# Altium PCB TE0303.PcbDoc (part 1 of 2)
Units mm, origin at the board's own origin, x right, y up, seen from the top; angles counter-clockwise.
Board outline 115 x 70 mm, 4 copper layers (L 01 (Top), L 02, L 03, L 04 (Bot)), stack 1.564 mm thick; 42 components, 141 nets, 429 pads, 134 vias.
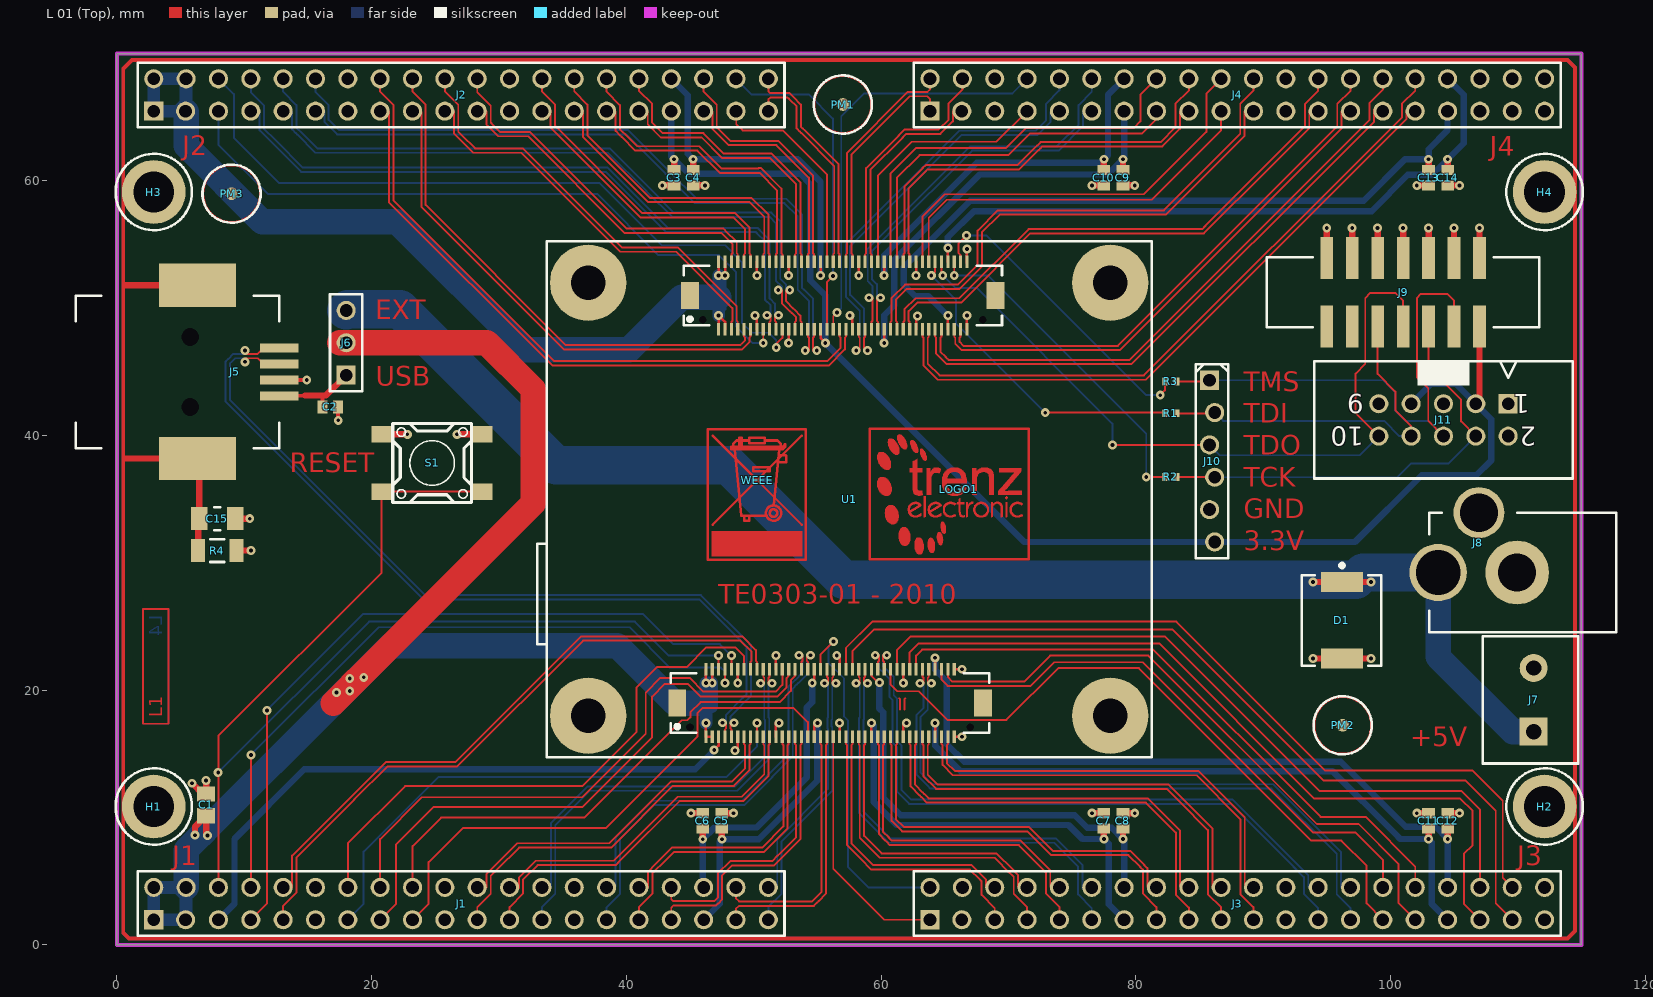
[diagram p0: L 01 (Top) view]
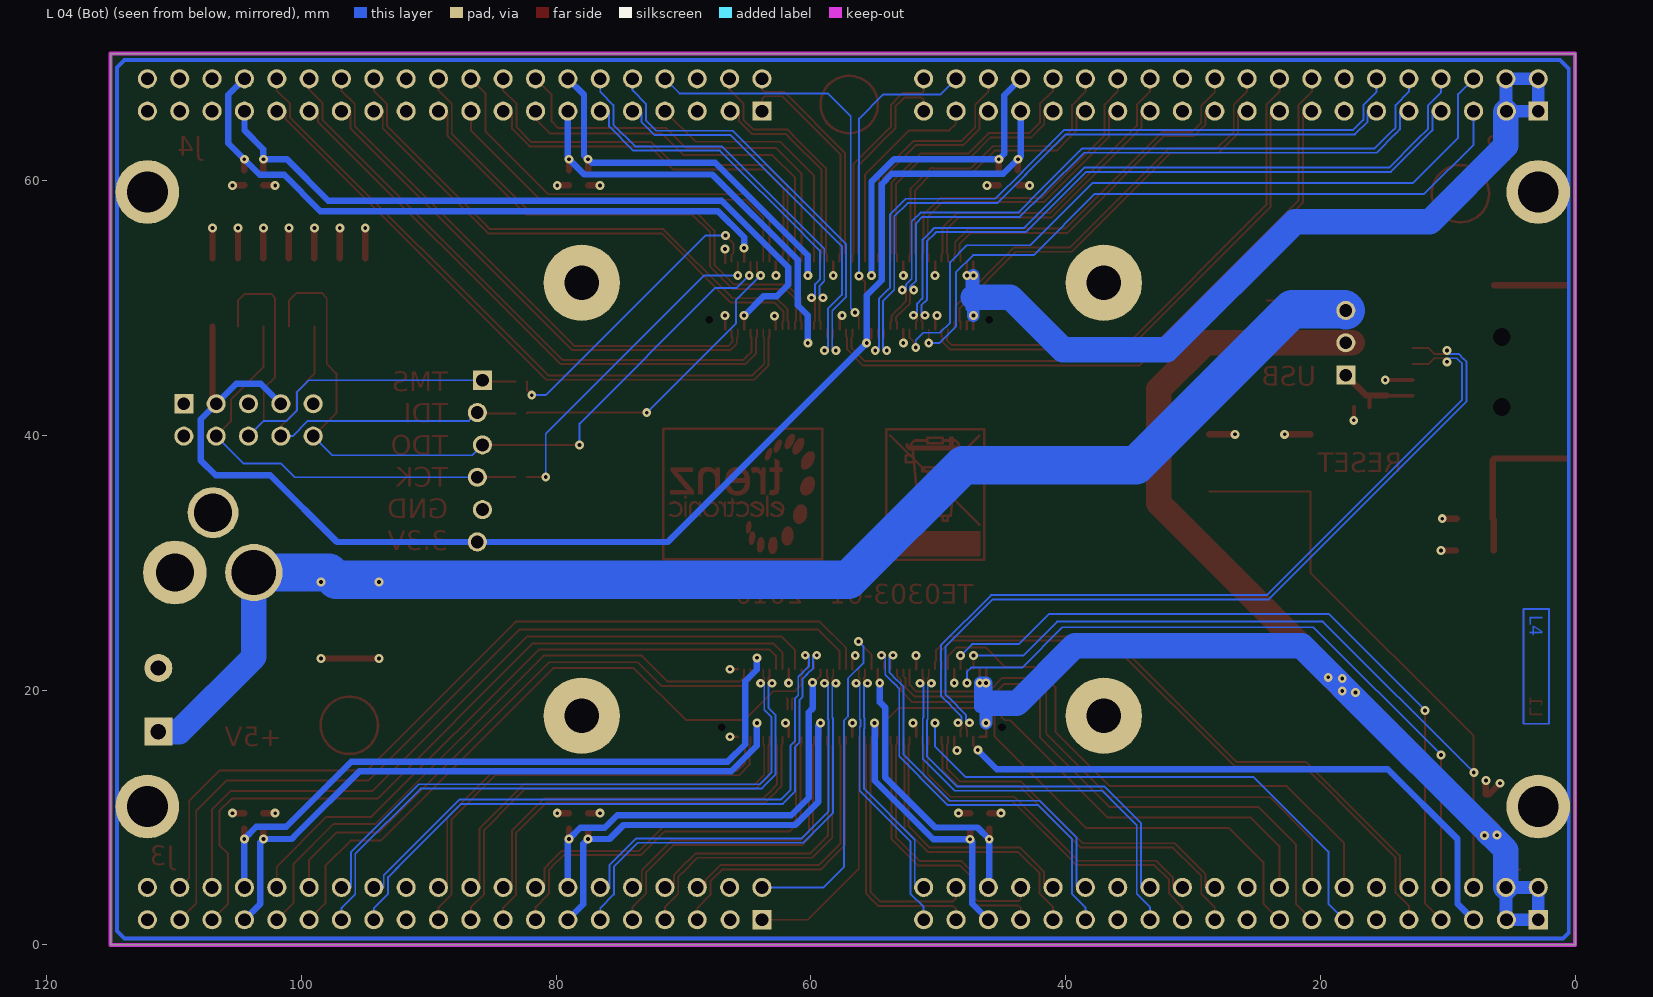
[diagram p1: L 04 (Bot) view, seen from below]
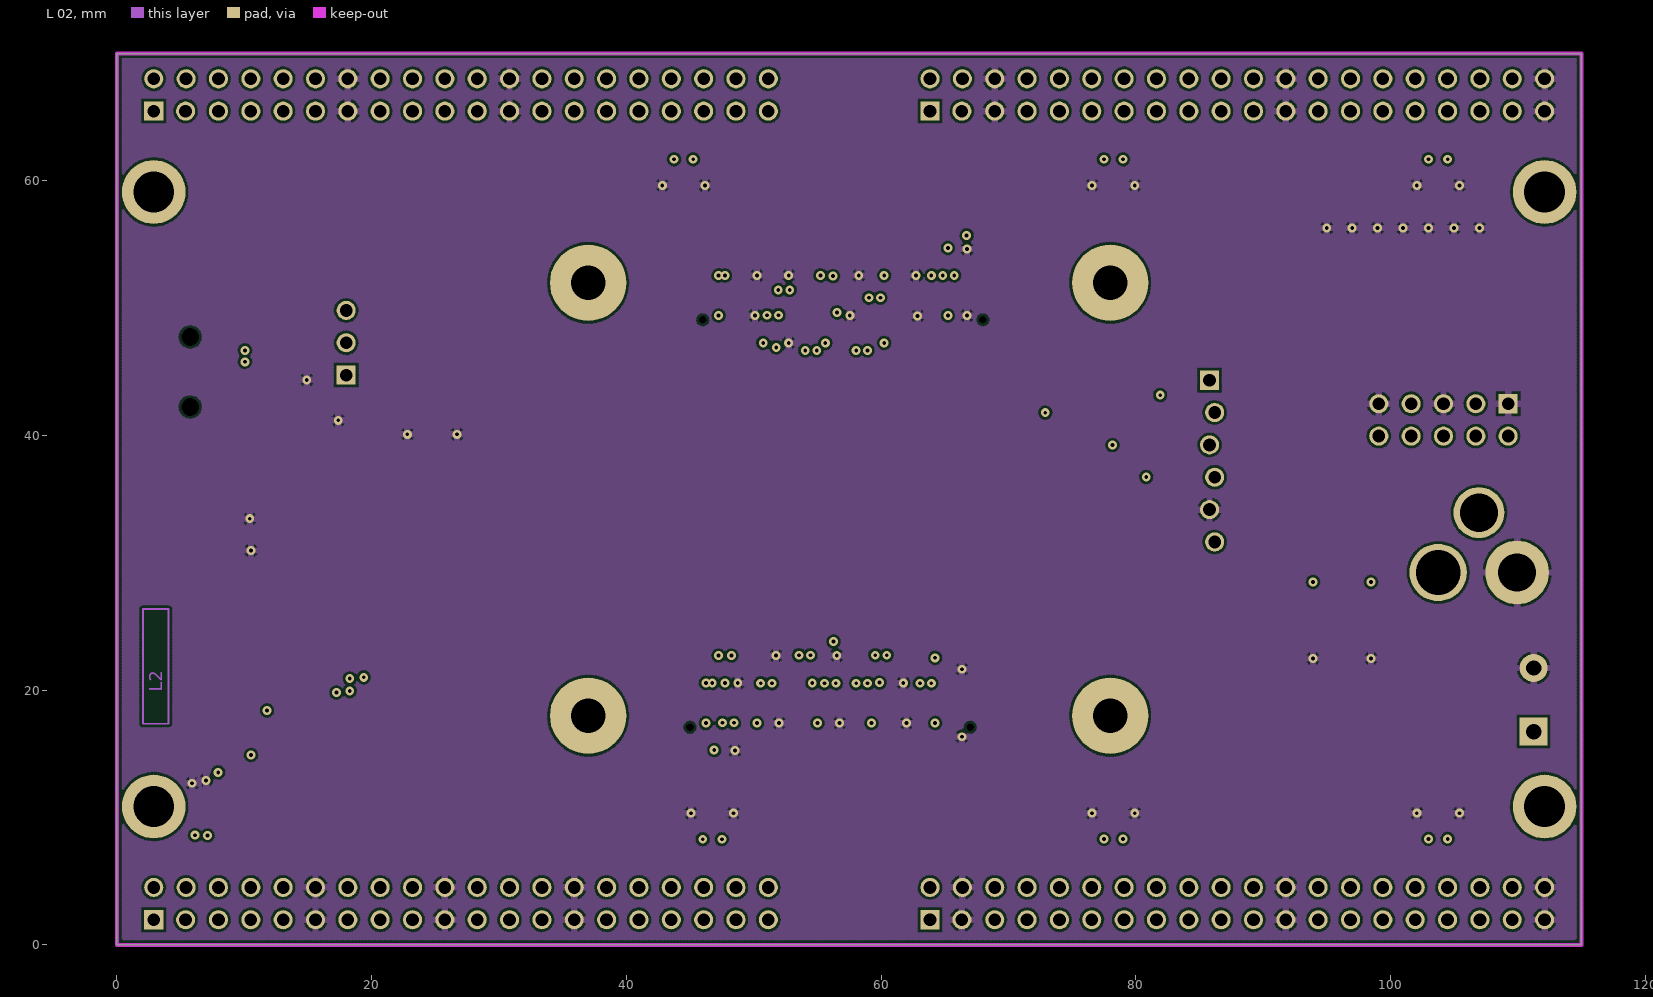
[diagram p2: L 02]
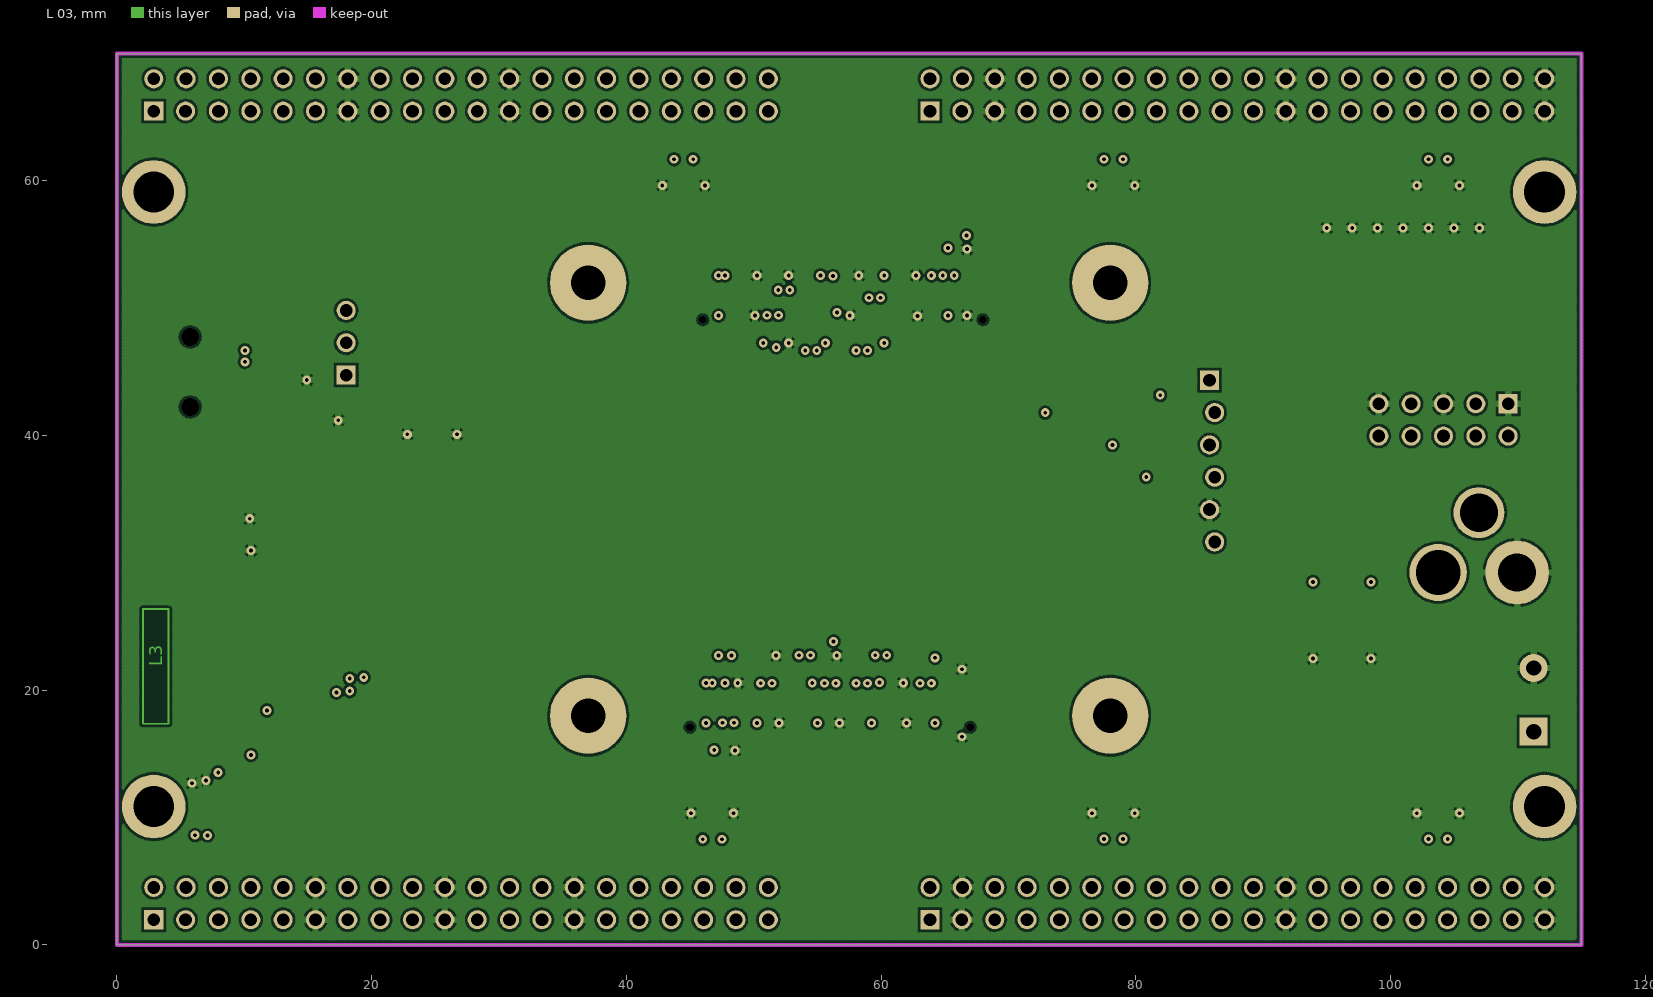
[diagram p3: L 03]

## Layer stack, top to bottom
L 01 (Top): signal copper 0.05
Dielectric: core 0.134, FR-4, Dk 4.8
L 02: signal copper 0.033
Dielectric: prepreg 1.13, FR-4, Dk 4.8
L 03: signal copper 0.033
Dielectric: core 0.134, FR-4, Dk 4.8
L 04 (Bot): signal copper 0.05

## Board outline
0,0 0,70 115,70 115,0

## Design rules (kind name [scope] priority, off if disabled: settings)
Clearance Clearance_Polygon [(InPolygon)] p1: gap=0.2
Clearance [All] p2: gap=0.19
ComponentClearance ComponentClearance_WEEE [(InComponent('WEEE'))] p1: gap=-20 collisioncheckmode=3 verticalgap=0.254 showdistances=FALSE
ComponentClearance ComponentClearance_LOGO [(InComponent('LOGO1'))] p2: gap=-50 collisioncheckmode=3 verticalgap=0 showdistances=FALSE
ComponentClearance [All] p3: gap=-0.05 collisioncheckmode=3 verticalgap=0.254 showdistances=FALSE
DiffPairsRouting [All] p1: maxlimit=1 minlimit=0.189 mostfreqgap=1 toplayer_maxgap=0.191 toplayer_prefgap=0.19 midlayer1_mingap=1 midlayer2_mingap=1 bottomlayer_maxgap=0.191 bottomlayer_prefgap=0.19 maxuncoupledlength=12.7
FabricationTestPointUsage TestPointUsage [All] p1: valid=0 allowmultiple=FALSE
FabricationTestpoint Testpoint [All] p1: side=3 testpointundercomponent=TRUE minsize=1.016 maxsize=2.54 preferedsize=1.524 minholesize=0 maxholesize=1.016 preferedholesize=0.813 testpointgrid=0.025 allowsidetop=TRUE allowsidebottom=TRUE usegrid=TRUE gridtolerance=0
HoleSize [All] p1: absolutevalues=TRUE maxlimit=5 minlimit=0.3 maxpercent=80.000 minpercent=20.000
MinimumAnnularRing [Not(InComponent('J7'))] p1: minimumring=0.2
PolygonConnect [All] p1: connectstyle=Relief reliefconductorwidth=0.5 reliefentries=4 polygonreliefangle="90 Angle"
RoutingLayers [All] p1: top layer_v5=TRUE mid layer 1_v5=FALSE mid layer 2_v5=FALSE bottom layer_v5=TRUE
RoutingVias [All] p1: holewidth=0.3 width=0.8 viastyle="Through Hole" minholewidth=0.3 minwidth=0.7 maxholewidth=1 maxwidth=3
SilkscreenOverComponentPads [All] p1: minsilkscreentomaskgap=0.254
SolderMaskExpansion SolderMaskExpansion_VIA [(IsVia)] p1: expansion=-10
SolderMaskExpansion [All] p2: expansion=0.102
Width Width_logo [InComponent(LOGO1)] p1: maxlimit=0.254 minlimit=0.004 preferedwidth=0.254
Width Width_100Ohm [(InNetClass('I100'))] p2: maxlimit=0.15 minlimit=0.15 preferedwidth=0.15
Width [All] p3: maxlimit=3 minlimit=0.15 preferedwidth=0.2
21 further rules are at their usual default settings.

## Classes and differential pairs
component class Main: H1 H2 H3 H4 LOGO1 PM1 PM2 PM3 WEEE
component class Signals: C1 C2 C15 D1 J5 J6 J7 J8 J9 J10 J11 R1 R2 R3 R4 S1 U1
component class Connector: C3 C4 C5 C6 C7 C8 C9 C10 C11 C12 C13 C14 J1 J2 J3 J4
net class I100: B0_L01_N B0_L01_P B0_L03_N B0_L03_P B0_L04_N B0_L04_P B0_L05_N B0_L05_P B0_L06_N B0_L06_P B0_L08_N B0_L08_P B0_L09_N B0_L09_P B0_L15_N B0_L15_P B0_L17_N B0_L17_P B0_L18_N B0_L18_P B0_L19_N B0_L19_P B0_L20_N B0_L20_P B0_L21_N B0_L21_P B0_L23_N B0_L23_P B0_L24_N B0_L24_P B2_GCLK_L13_N B2_GCLK_L13_P B2_L04_N B2_L04_P B2_L05_N B2_L05_P B2_L06_N B2_L06_P B2_L07_N B2_L07_P B2_L09_N B2_L09_P B2_L10_N B2_L10_P B2_L18_N B2_L18_P B2_L19_N B2_L19_P B2_L20_N B2_L20_P B2_L21_N B2_L21_P B2_L22_N B2_L22_P B2_L24_N B2_L24_P B2B_D_N B2B_D_P B3_L01_N B3_L01_P B3_L02_N B3_L02_P B3_L03_N B3_L03_P B3_L07_N B3_L07_P B3_L17_N B3_L17_P B3_L19_N B3_L19_P B3_L20_N B3_L20_P B3_L21_N B3_L21_P B3_L22_N B3_L22_P B3_L23_N B3_L23_P GCLK_L11_N GCLK_L11_P GCLK_L12_N GCLK_L12_P GCLK_L13_N GCLK_L13_P GCLK_L14_N GCLK_L14_P
differential pair B0_L01: +B0_L01_P -B0_L01_N
differential pair B0_L03: +B0_L03_P -B0_L03_N
differential pair B0_L04: +B0_L04_P -B0_L04_N
differential pair B0_L05: +B0_L05_P -B0_L05_N
differential pair B0_L06: +B0_L06_P -B0_L06_N
differential pair B0_L08: +B0_L08_P -B0_L08_N
differential pair B0_L09: +B0_L09_P -B0_L09_N
differential pair B0_L15: +B0_L15_P -B0_L15_N
differential pair B0_L17: +B0_L17_P -B0_L17_N
differential pair B0_L18: +B0_L18_P -B0_L18_N
differential pair B0_L19: +B0_L19_P -B0_L19_N
differential pair B0_L20: +B0_L20_P -B0_L20_N
differential pair B0_L21: +B0_L21_P -B0_L21_N
differential pair B0_L23: +B0_L23_P -B0_L23_N
differential pair B0_L24: +B0_L24_P -B0_L24_N
differential pair B2_GCLK_L13: +B2_GCLK_L13_P -B2_GCLK_L13_N
differential pair B2_L04: +B2_L04_P -B2_L04_N
differential pair B2_L06: +B2_L06_P -B2_L06_N
differential pair B2_L07: +B2_L07_P -B2_L07_N
differential pair B2_L09: +B2_L09_P -B2_L09_N
differential pair B2_L18: +B2_L18_P -B2_L18_N
differential pair B2_L19: +B2_L19_P -B2_L19_N
differential pair B2_L20: +B2_L20_P -B2_L20_N
differential pair B2_L21: +B2_L21_P -B2_L21_N
differential pair B2_L22: +B2_L22_P -B2_L22_N
differential pair B2_L24: +B2_L24_P -B2_L24_N
differential pair B2B_D: +B2B_D_P -B2B_D_N
differential pair B3_L01: +B3_L01_P -B3_L01_N
differential pair B3_L03: +B3_L03_P -B3_L03_N
differential pair B3_L07: +B3_L07_P -B3_L07_N
differential pair B3_L17: +B3_L17_P -B3_L17_N
differential pair B3_L19: +B3_L19_P -B3_L19_N
differential pair B3_L20: +B3_L20_P -B3_L20_N
differential pair B3_L21: +B3_L21_P -B3_L21_N
differential pair B3_L22: +B3_L22_P -B3_L22_N
differential pair B3_L23: +B3_L23_P -B3_L23_N
differential pair GCLK_L11: +GCLK_L11_P -GCLK_L11_N
differential pair GCLK_L12: +GCLK_L12_P -GCLK_L12_N
differential pair GCLK_L13: +GCLK_L13_P -GCLK_L13_N
differential pair GCLK_L14: +GCLK_L14_P -GCLK_L14_N
differential pair B2_L10: +B2_L10_P -B2_L10_N
differential pair B3_L02: +B3_L02_P -B3_L02_N
differential pair B2_L05: +B2_L05_P -B2_L05_N

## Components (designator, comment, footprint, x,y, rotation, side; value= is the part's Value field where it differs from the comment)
C1 "10µF" CAPC2012N 7,11 r270 top
C2 "100nF" CAPC1608N 16.75,42.25 r0 top
C3 "100nF" CAPC1608N 43.75,60.25 r270 top
C4 "100nF" CAPC1608N 45.25,60.25 r270 top
C5 "100nF" CAPC1608N 47.5,9.75 r90 top
C6 "100nF" CAPC1608N 46,9.75 r90 top
C7 "100nF" CAPC1608N 77.5,9.75 r90 top
C8 "100nF" CAPC1608N 79,9.75 r90 top
C9 "100nF" CAPC1608N 79,60.25 r270 top
C10 "100nF" CAPC1608N 77.5,60.25 r270 top
C11 "100nF" CAPC1608N 103,9.75 r90 top
C12 "100nF" CAPC1608N 104.5,9.75 r90 top
C13 "100nF" CAPC1608N 103,60.25 r270 top
C14 "100nF" CAPC1608N 104.5,60.25 r270 top
C15 "100pF" CAPC3216N 7.875,33.475 r0 top
D1 "MBRS340T3" MBRS340T3 96.2,25.5 r90 top
H1 "MHole3.2mm" MHole3_2mm 2.89,10.87 r0 top locked
H2 "MHole3.2mm" MHole3_2mm 112.11,10.87 r0 top locked
H3 "MHole3.2mm" MHole3_2mm 2.89,59.13 r0 top locked
H4 "MHole3.2mm" MHole3_2mm 112.11,59.13 r0 top locked
J1 "STIFTLEISTE2.54 OG 2R-40" "STIFTLEISTE2_54 OG 2R-40" 27.02,3.25 r0 top locked
J2 "STIFTLEISTE2.54 OG 2R-40" "STIFTLEISTE2_54 OG 2R-40" 27.02,66.75 r0 top locked
J3 "STIFTLEISTE2.54 OG 2R-40" "STIFTLEISTE2_54 OG 2R-40" 87.98,3.25 r0 top locked
J4 "STIFTLEISTE2.54 OG 2R-40" "STIFTLEISTE2_54 OG 2R-40" 87.98,66.75 r0 top locked
J5 "USB B SMD" "USB B SMD" 5.75,45 r270 top locked
J6 "JUMPER2.54-3" JUMPER2_54-3 18,44.75 r270 top
J7 "ARK500-2" ARK500-2 111.25,19.25 r90 top locked
J8 "2.5MM_BUCHSE" WS-DC001 103.75,29.25 r180 top locked
J9 "WANNE2mm2R-14" WANNE2mm2R-14 101,51.25 r180 top
J10 "Stiftleiste versetzt 1-reihig, 6pol." "STIFTLEISTE2_54 OG 1R-6V" 86,38 r270 top
J11 "WANNE2,54-10 GERADE" "WANNE2,54-10 GERADE" 109.25,42.5 r180 top locked
LOGO1 "LOGO TOP" "Logo Top" 66.1,35.775 r0 top
PM1 "FIDU-DOT" FIDU-DOT 57,66 r0 top locked
PM2 "FIDU-DOT" FIDU-DOT 96.25,17.25 r0 top
PM3 "FIDU-DOT" FIDU-DOT 9,59 r0 top locked
R1 "100R" RESC1005N 82.75,41.75 r0 top
R2 "100R" RESC1005N 82.75,36.75 r0 top
R3 "100R" RESC1005N 82.75,44.25 r0 top
R4 "1M" RESC3216N 7.875,30.975 r0 top
S1 "SW PB DTSM61N" DTSM61N 24.75,37.85 r180 top
U1 "TE0300-01" TE0300-01 57.5,35 r90 top locked
WEEE "WEEE TOP" WEEETOP_10_25mm 50.275,36.5 r0 top

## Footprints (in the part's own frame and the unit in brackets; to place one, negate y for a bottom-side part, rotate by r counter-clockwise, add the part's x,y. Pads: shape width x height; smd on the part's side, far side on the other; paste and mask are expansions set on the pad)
ARK500-2 [mm] "AR-Klemmen 250V 2pol. grau"
  rect 2.2x2.2 hole 1.2: 1(-2.5,0)
  round 2.2 hole 1.2: 2(2.5,0)
  silkscreen extent -5,-3.5 5,4, body extent -3,-3 3,3, height 10
CAPC1608N [mm] "Vishay VJ0603 1.6 x 0.8 (+0.15/-0.1) 0.4 +/- 0,15mm Kontakte"
  rect 0.8x1 smd: 1(-0.6,0) 2(0.6,0)
  body extent -1.15,-0.65 1.15,0.65, height 0.95
CAPC2012N [mm] "Vishay VJ0805 2 x 1.25 +/- 0.15, 0.5 +/- 0,2 Kontakte"
  rect 1.2x1.4 smd: 1(-0.85,0) 2(0.85,0)
  body extent -1.7,-0.95 1.7,0.95, height 1.35
CAPC3216N [mm] "Vishay VJ1206 3.2 x 1.6 (+/- 0.15), 0.4mm - 0.8mm Kontakte"
  rect 1.3x1.8 smd: 1(-1.4,0) 2(1.4,0)
  silkscreen extent -0.25,-0.9 0.25,0.9, body extent -2.3,-1.15 2.3,1.15, height 1.8
DTSM61N [mm] "SMD-Taster"
  rect 1.55x1.3 smd: 1(-3.975,2.25) 1(3.975,2.25) 2(-3.975,-2.25) 2(3.975,-2.25)
  silkscreen extent -3.1,-3.1 3.1,3.1
FIDU-DOT [mm]
  round 1 smd paste-1 mask+2: 0(0,0)
  L 01 (Top) circle w0.2: c0,0 r2.25
  silkscreen extent -2.28,-2.29 2.29,2.29
JUMPER2_54-3 [mm]
  rect 1.5x1.5 hole 1: 1(0,0)
  round 1.5 hole 1: 2(-2.54,0) 3(-5.08,0)
  silkscreen extent -6.35,-1.27 1.27,1.27
"Logo Top" [mm]
  L 01 (Top) drawing of 1838 lines, arcs and shapes, not listed
MBRS340T3 [mm]
  rect 1.6x3.27 smd: 1(3,0) 2(-3,0)
  silkscreen extent -3.56,-3.07 4.45,3.15, body extent -4.56,-4.07 4.55,4.15, height 2.6
MHole3_2mm [mm]
  round 5 hole 3.2: 1(0,0)
  silkscreen extent -3,-3 3,3
RESC1005N [mm] "Vishay D0402 1 x 0.5mm (+/- 0.05), 0.2mm +/-0.1mm Kontakte"
  rect 0.5x0.6 smd: 1(-0.45,0) 2(0.45,0)
  body extent -0.85,-0.5 0.85,0.5, height 0.4
RESC3216N [mm] "Vishay D1206 3.2 x 1.6 (+/- 0.15), 0.2mm - 0.6mm Kontakte"
  rect 1.1x1.8 smd: 1(-1.5,0) 2(1.5,0)
  silkscreen extent -0.55,-0.9 0.55,0.9, body extent -2.3,-1.15 2.3,1.15, height 0.6
"STIFTLEISTE2_54 OG 1R-6V" [mm]
  rect 1.5x1.5 hole 1: 1(-6.35,-0.2)
  round 1.5 hole 1: 2(-3.81,0.2) 3(-1.27,-0.2) 4(1.27,0.2) 5(3.81,-0.2) 6(6.35,0.2)
  silkscreen extent -7.62,-1.27 7.62,1.27, body extent -8.62,-2.27 8.62,2.27, height 9
"STIFTLEISTE2_54 OG 2R-40" [mm]
  rect 1.5x1.5 hole 1: 1(-24.13,-1.27)
  round 1.5 hole 1: 2(-24.13,1.27) 3(-21.63,-1.27) 4(-21.59,1.27) 5(-19.05,-1.27) 6(-19.05,1.27) 7(-16.51,-1.27) 8(-16.51,1.27) 9(-13.97,-1.27) 10(-13.97,1.27) 11(-11.43,-1.27) 12(-11.43,1.27) 13(-8.89,-1.27) 14(-8.89,1.27) 15(-6.35,-1.27) 16(-6.35,1.27) 17(-3.81,-1.27) 18(-3.81,1.27) 19(-1.27,-1.27) 20(-1.27,1.27) 21(1.27,-1.27) 22(1.27,1.27) 23(3.81,-1.27) 24(3.81,1.27) 25(6.35,-1.27) 26(6.35,1.27) 27(8.89,-1.27) 28(8.89,1.27) 29(11.43,-1.27) 30(11.43,1.27) 31(13.97,-1.27) 32(13.97,1.27) 33(16.51,-1.27) 34(16.51,1.27) 35(19.05,-1.27) 36(19.05,1.27) 37(21.59,-1.27) 38(21.59,1.27) 39(24.13,-1.27) 40(24.13,1.27)
  silkscreen extent -25.4,-2.54 25.4,2.54, body extent -26.4,-3.54 26.4,3.54, height 11.3
TE0300-01 [mm] "USB-Modul"
  round 6 hole 2.72: 1(-17,20.5) 2(-17,-20.5) 3(17,20.5) 4(17,-20.5)
  round 0 hole 0.6 unplated: A(-17.9,12.5) A(14.1,11.5) B(-17.9,-9.5) B(14.1,-10.5)
  rect 2.1x1.4 smd: G1(-16,13.5) G1(16,12.5) G2(-16,-10.5) G2(16,-11.5)
  rect 1x0.25 smd: J4-1(13.35,10.25) J4-2(18.65,10.25) J4-3(13.35,9.75) J4-4(18.65,9.75) J4-5(13.35,9.25) J4-6(18.65,9.25) J4-7(13.35,8.75) J4-8(18.65,8.75) J4-9(13.35,8.25) J4-10(18.65,8.25) J4-11(13.35,7.75) J4-12(18.65,7.75) J4-13(13.35,7.25) J4-14(18.65,7.25) J4-15(13.35,6.75) J4-16(18.65,6.75) J4-17(13.35,6.25) J4-18(18.65,6.25) J4-19(13.35,5.75) J4-20(18.65,5.75) J4-21(13.35,5.25) J4-22(18.65,5.25) J4-23(13.35,4.75) J4-24(18.65,4.75) J4-25(13.35,4.25) J4-26(18.65,4.25) J4-27(13.35,3.75) J4-28(18.65,3.75) J4-29(13.35,3.25) J4-30(18.65,3.25) J4-31(13.35,2.75) J4-32(18.65,2.75) J4-33(13.35,2.25) J4-34(18.65,2.25) J4-35(13.35,1.75) J4-36(18.65,1.75) J4-37(13.35,1.25) J4-38(18.65,1.25) J4-39(13.35,0.75) J4-40(18.65,0.75) J4-41(13.35,0.25) J4-42(18.65,0.25) J4-43(13.35,-0.25) J4-44(18.65,-0.25) J4-45(13.35,-0.75) J4-46(18.65,-0.75) J4-47(13.35,-1.25) J4-48(18.65,-1.25) J4-49(13.35,-1.75) J4-50(18.65,-1.75) J4-51(13.35,-2.25) J4-52(18.65,-2.25) J4-53(13.35,-2.75) J4-54(18.65,-2.75) J4-55(13.35,-3.25) J4-56(18.65,-3.25) J4-57(13.35,-3.75) J4-58(18.65,-3.75) J4-59(13.35,-4.25) J4-60(18.65,-4.25) J4-61(13.35,-4.75) J4-62(18.65,-4.75) J4-63(13.35,-5.25) J4-64(18.65,-5.25) J4-65(13.35,-5.75) J4-66(18.65,-5.75) J4-67(13.35,-6.25) J4-68(18.65,-6.25) J4-69(13.35,-6.75) J4-70(18.65,-6.75) J4-71(13.35,-7.25) J4-72(18.65,-7.25) J4-73(13.35,-7.75) J4-74(18.65,-7.75) J4-75(13.35,-8.25) J4-76(18.65,-8.25) J4-77(13.35,-8.75) J4-78(18.65,-8.75) J4-79(13.35,-9.25) J4-80(18.65,-9.25) J5-1(-18.65,11.25) J5-2(-13.35,11.25) J5-3(-18.65,10.75) J5-4(-13.35,10.75) J5-5(-18.65,10.25) J5-6(-13.35,10.25) J5-7(-18.65,9.75) J5-8(-13.35,9.75) J5-9(-18.65,9.25) J5-10(-13.35,9.25) J5-11(-18.65,8.75) J5-12(-13.35,8.75) J5-13(-18.65,8.25) J5-14(-13.35,8.25) J5-15(-18.65,7.75) J5-16(-13.35,7.75) J5-17(-18.65,7.25) J5-18(-13.35,7.25) J5-19(-18.65,6.75) J5-20(-13.35,6.75) J5-21(-18.65,6.25) J5-22(-13.35,6.25) J5-23(-18.65,5.75) J5-24(-13.35,5.75) J5-25(-18.65,5.25) J5-26(-13.35,5.25) J5-27(-18.65,4.75) J5-28(-13.35,4.75) J5-29(-18.65,4.25) J5-30(-13.35,4.25) J5-31(-18.65,3.75) J5-32(-13.35,3.75) J5-33(-18.65,3.25) J5-34(-13.35,3.25) J5-35(-18.65,2.75) J5-36(-13.35,2.75) J5-37(-18.65,2.25) J5-38(-13.35,2.25) J5-39(-18.65,1.75) J5-40(-13.35,1.75) J5-41(-18.65,1.25) J5-42(-13.35,1.25) J5-43(-18.65,0.75) J5-44(-13.35,0.75) J5-45(-18.65,0.25) J5-46(-13.35,0.25) J5-47(-18.65,-0.25) J5-48(-13.35,-0.25) J5-49(-18.65,-0.75) J5-50(-13.35,-0.75) J5-51(-18.65,-1.25) J5-52(-13.35,-1.25) J5-53(-18.65,-1.75) J5-54(-13.35,-1.75) J5-55(-18.65,-2.25) J5-56(-13.35,-2.25) J5-57(-18.65,-2.75) J5-58(-13.35,-2.75) J5-59(-18.65,-3.25) J5-60(-13.35,-3.25) J5-61(-18.65,-3.75) J5-62(-13.35,-3.75) J5-63(-18.65,-4.25) J5-64(-13.35,-4.25) J5-65(-18.65,-4.75) J5-66(-13.35,-4.75) J5-67(-18.65,-5.25) J5-68(-13.35,-5.25) J5-69(-18.65,-5.75) J5-70(-13.35,-5.75) J5-71(-18.65,-6.25) J5-72(-13.35,-6.25) J5-73(-18.65,-6.75) J5-74(-13.35,-6.75) J5-75(-18.65,-7.25) J5-76(-13.35,-7.25) J5-77(-18.65,-7.75) J5-78(-13.35,-7.75) J5-79(-18.65,-8.25) J5-80(-13.35,-8.25)
  silkscreen extent -20.25,-23.75 20.25,24.51, body extent -2.5,-2.5 2.5,2.5, height 11
"USB B SMD" [mm]
  rect 0.7x3 smd: 1(1.875,7) 2(-0.625,7) 3(-1.875,7) 4(0.625,7)
  round 0 hole 1.4 unplated: A(2.75,0) B(-2.75,0)
  rect 3.4x6.04 smd: S1(6.8,0.58) S2(-6.8,0.58)
  silkscreen extent -6,-9 6,7, body extent -9.5,-10 9.5,9.5, height 11
"WANNE2,54-10 GERADE" [mm] "Connector; IDC, Low Profile Male Header, Thru-Hole; 10 Position; Vertical; Pitch 2.54 mm; Body 20.32 x 9.2 x 9.45 mm (LxWxH)"
  rect 1.5x1.5 hole 1: 1(0,0)
  round 1.5 hole 1: 2(0,2.54) 3(2.54,0) 4(2.54,2.54) 5(5.08,0) 6(5.08,2.54) 7(7.62,0) 8(7.62,2.54) 9(10.16,0) 10(10.16,2.54)
  silkscreen extent -5.08,-3.33 15.24,5.87
WANNE2mm2R-14 [mm]
  rect 1x3.3 smd: 1(-6,-2.685) 2(-6,2.685) 3(-4,-2.685) 4(-4,2.685) 5(-2,-2.685) 6(-2,2.685) 7(0,-2.685) 8(0,2.685) 9(2,-2.685) 10(2,2.685) 11(4,-2.685) 12(4,2.685) 13(6,-2.685) 14(6,2.685)
  silkscreen extent -10.7,-2.75 10.7,2.75, body extent -11.6,-4.6 11.6,4.6, height 6.5
WEEETOP_10_25mm [mm]
  L 01 (Top) circle w0.2: c1.283,-2.583 r0.3
  L 01 (Top) circle w0.2: c1.283,-2.583 r0.6
  L 01 (Top) region: -3.574,-6.001 3.551,-6.001 3.551,-4.001 -3.574,-4.001
  L 01 (Top) lines w0.2: -3.499,-3.501 3.501,3.499 ; -3.499,3.499 3.501,-3.501 ; -1.892,2.617 -1.892,2.842 -1.617,3.117 -0.617,3.117 ; -1.767,2.417 -1.267,-2.783 0.733,-2.783 ; -1.617,2.417 1.983,2.417 ; -1.417,2.617 -1.417,3.317 -1.217,3.317 -1.217,2.617 ; -1.017,-2.783 -1.017,-3.183 -0.617,-3.183 -0.617,-2.783 ; 0.583,3.117 0.783,3.117 1.583,3.117 1.858,2.842 1.858,2.617 ; 1.293,-1.983 1.733,2.417 ; 1.647,1.415 2.281,1.415 2.283,1.417 2.283,1.917 2.252,1.948 1.686,1.948 ; 1.983,2.417 -2.017,2.417 -2.017,2.617 1.983,2.617 2.183,2.817 2.183,2.617 1.983,2.417 ; -3.874,-6.251 -3.874,3.999 3.826,3.999 3.826,-6.251 -3.874,-6.251 ; -0.617,2.917 -0.617,3.317 0.583,3.317 0.583,2.917 -0.617,2.917 ; -0.317,0.717 -0.317,1.017 0.983,1.017 0.983,0.717 -0.317,0.717
WS-DC001 [mm]
  round 4.5 hole 3.5: 1(0,0)
  round 4 hole 3: 2(-3.2,-4.7)
  round 5 hole 3: 3(-6.2,0)
  silkscreen extent -14,-4.7 0.7,4.7, body extent -3,-3 3,3, height 11.3

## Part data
C1: library part 22478
C2 C3 C4 C5 C6 C7 C8 C9 C10 C11 C12 C13 C14: library part 21382
C15: library part 22679
D1: library part 22887
H1 H2 H3 H4: library part 22898
J1 J2 J3 J4: library part 22320
J5: library part 22990
J6: library part 22328, "Jumper"
J7: library part 20123
J8: library part 22398, "2.5mm Stromversorgungsbuchse"
J9: library part 22744
J10: library part 22911
J11: library part 20125
LOGO1: library part 22901
PM1 PM2 PM3: library part 22906
R1 R2 R3: library part 22507
R4: library part 22757
S1: library part 22596
WEEE: library part 22300

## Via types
v1: diameter 0.7, hole 0.3, L 01 (Top) to L 04 (Bot), 134 vias

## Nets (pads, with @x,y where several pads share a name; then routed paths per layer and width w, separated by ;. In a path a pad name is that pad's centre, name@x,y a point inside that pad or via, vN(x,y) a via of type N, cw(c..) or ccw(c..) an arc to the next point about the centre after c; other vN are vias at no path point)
1V2_1: C11.1 J3.33 U1.J5-73 | length 52.4
  L 01 (Top) w0.2: U1.J5-73@64.25,16.35 v1(64.25,17.425)
  L 01 (Top) w0.5: v1(103,8.325) C11.1@103,9.15
  L 04 (Bot) w0.5: v1(64.25,17.425) 64.25,15.65 66.25,13.65 95.45,13.65 100.332,8.768 100.775,8.325 v1(103,8.325) 103.25,8.075 103.25,3.22 J3.33@104.49,1.98
1V2_2: C12.1 J3.34 U1.J5-74 | length 55.1
  L 01 (Top) w0.2: U1.J5-74@64.25,21.65 v1(64.25,22.55)
  L 01 (Top) w0.5: v1(104.5,8.325) C12.1@104.5,9.15
  L 04 (Bot) w0.5: v1(64.25,22.55) 64.25,21.6 65.15,20.7 65.15,15.775 66.55,14.375 96.1,14.375 101.2,9.275 103.55,9.275 v1(104.5,8.325) 104.5,4.53 J3.34@104.49,4.52
1V2_3: C13.1 J4.33 U1.J4-73 | length 56.9
  L 01 (Top) w0.2: U1.J4-73@65.25,48.35 v1(65.25,49.425)
  L 01 (Top) w0.5: C13.1@103,60.85 v1(103,61.7)
  L 04 (Bot) w0.5: v1(65.25,49.425) 63.725,50.95 62.675,50.95 61.775,51.85 61.775,53.225 67,58.45 97.9,58.45 101.15,61.7 v1(103,61.7) 103,62.5 104.49,63.99 J4.33@104.49,65.48
1V2_4: C14.1 J4.34 U1.J4-74 | length 51.9
  L 01 (Top) w0.2: U1.J4-74@65.25,53.65 v1(65.25,54.725)
  L 01 (Top) w0.5: C14.1@104.5,60.85 v1(104.5,61.7)
  L 04 (Bot) w0.5: v1(65.25,54.725) 65.25,55.575 67.3,57.625 98.525,57.625 101.375,60.475 103.275,60.475 v1(104.5,61.7) 105.75,62.95 105.75,66.76 J4.34@104.49,68.02
2V5_1: C7.1 J3.13 U1.J5-53 | length 34.5
  L 01 (Top) w0.2: U1.J5-53@59.25,16.35 v1(59.25,17.425)
  L 01 (Top) w0.5: v1(77.5,8.325) C7.1@77.5,9.15
  L 04 (Bot) w0.5: v1(59.25,17.425) 59.425,17.25 59.425,11.225 61.225,9.425 74.725,9.425 75.825,8.325 v1(77.5,8.325) 77.875,7.95 77.875,3.195 J3.13@79.09,1.98
2V5_2: C8.1 J3.14 U1.J5-54 | length 35.4
  L 01 (Top) w0.15: U1.J5-54@59.25,21.65 59.25,21.125 59.775,20.6 v1(59.875,20.6)
  L 01 (Top) w0.5: v1(79,8.325) C8.1@79,9.15
  L 04 (Bot) w0.5: v1(59.875,20.6) 59.875,18.575 60.175,18.275 60.175,11.55 61.55,10.175 75.225,10.175 76.2,9.2 78.125,9.2 v1(79,8.325) 79.09,8.235 J3.14@79.09,4.52
2V5_3: C9.1 J4.13 U1.J4-53 | length 33.8
  L 01 (Top) w0.2: v1(60.25,47.275) U1.J4-53@60.25,48.35
  L 01 (Top) w0.5: C9.1@79,60.85 v1(79,61.7)
  L 04 (Bot) w0.5: v1(60.25,47.275) 60.25,49.45 61.05,50.25 61.05,53.8 67.75,60.5 77.8,60.5 v1(79,61.7) 79.09,61.79 J4.13@79.09,65.48
2V5_4: C10.1 J4.14 U1.J4-54 | length 30.9
  L 01 (Top) w0.2: v1(60.25,52.575) U1.J4-54@60.25,53.65
  L 01 (Top) w0.5: C10.1@77.5,60.85 v1(77.5,61.7)
  L 04 (Bot) w0.5: v1(60.25,52.575) 60.25,54.15 67.525,61.425 77.225,61.425 v1(77.5,61.7) 77.825,62.025 77.825,66.755 J4.14@79.09,68.02
3V3_1: C5.1 J1.35 U1.J5-35 | length 22.8
  L 01 (Top) w0.2: U1.J5-35@54.75,16.35 v1@54.75,17.425
  L 01 (Top) w0.5: v1(47.5,8.3) C5.1@47.5,9.15
  L 04 (Bot) w0.5: J1.35@46.07,1.98 47.325,3.235 47.325,8.125 v1(47.5,8.3) 50.4,8.3 55,12.9 v1(55,17.425)
3V3_2: C6.1 J1.36 U1.J5-36 | length 23.6
  L 01 (Top) w0.2: v1(54.6,20.575) 54.75,20.725 U1.J5-36@54.75,21.65
  L 01 (Top) w0.5: v1(46,8.3) C6.1@46,9.15
  L 04 (Bot) w0.5: J1.36@46.07,4.52 46,4.59 v1(46,8.3) 46.925,9.225 50.25,9.225 54.175,13.15 54.175,18.65 54.6,19.075 v1(54.6,20.575)
3V3_3: C3.1 J2.33 J9.2 J10.6 J11.3 J11.7 U1.J4-33 | length 109.4
  L 01 (Top) w0.2: U1.J4-33@55.25,48.35 55.25,47.65 v1(55.625,47.275)
  L 01 (Top) w0.5: C3.1@43.75,60.85 v1(43.75,61.7) ; J11.3@106.71,42.5 107,42.79 J9.2@107,48.565
  L 04 (Bot) w0.5: J2.33@43.53,65.48 43.53,61.92 v1(43.75,61.7) 44.9,60.55 53.649,60.55 54.45,59.749 54.45,52.2 55.625,51.025 v1(55.625,47.275) 71.25,31.65 J10.6@86.2,31.65 97.225,31.65 102.45,36.875 106.75,36.875 107.925,38.05 107.925,41.285 J11.3@106.71,42.5 105.135,44.075 103.205,44.075 J11.7@101.63,42.5
3V3_4: C4.1 J2.34 U1.J4-34 | length 27
  L 01 (Top) w0.2: v1(55.25,52.575) U1.J4-34@55.25,53.65
  L 01 (Top) w0.5: C4.1@45.25,60.85 v1(45.25,61.7)
  L 04 (Bot) w0.5: J2.34@43.53,68.02 44.825,66.725 44.825,62.125 v1(45.25,61.7) 53.475,61.7 55.25,59.925 v1(55.25,52.575)
5VOUT: J1.5 U1.J5-5 | length 48.6
  L 01 (Top) w0.2: v1(46.9,15.3) 47.25,15.65 U1.J5-5@47.25,16.35
  L 04 (Bot) w0.5: J1.5@7.97,1.98 9.225,3.235 9.225,8.325 14.7,13.8 45.4,13.8 v1(46.9,15.3)
+VB2B: C1.2 J1.1 J1.2 J1.3 J1.4 J6.2 U1.J5-1 U1.J5-2 U1.J5-3 U1.J5-4 | length 122.8
  L 01 (Top) w0.2: v1(46.25,17.425) U1.J5-1@46.25,16.35 U1.J5-3@46.75,16.35 ; v1(46.25,20.575) U1.J5-2@46.25,21.65 ; v1(46.75,20.575) U1.J5-4@46.75,21.65
  L 01 (Top) w0.5: v1(6.13,8.62) 6.13,9.28 C1.2@7,10.15 7,8.7 v1(7.105,8.595)
  L 01 (Top) w2: 16.975,18.975 17.525,19.525 18.112,20.112 18.6,20.6 19.2,21.2 32.675,34.675 32.675,43.65 29.035,47.29 J6.2@18,47.29 J6.2@17.5,47.29
  L 04 (Bot) w1: v1(46.25,17.425) v1(46.25,20.575) 46.71,20.575 46.71,18.715 ; J1.1@2.89,1.98 J1.3@5.39,1.98 5.43,2.02 J1.4@5.43,4.52 J1.2@2.89,4.52 J1.1@2.89,1.98
  L 04 (Bot) w2: J1.4@5.43,4.52 5.43,7.455 6.362,8.387 6.622,8.647 6.837,8.862 17.512,19.538 18.1,20.125 18.587,20.612 19.187,21.213 21.475,23.5 39.3,23.5 43.825,18.975 46.1,18.975
  other v1: 17.23,19.82 18.28,19.945 18.28,20.92 19.38,21.02
+VCON: D1.1 J6.3 J7.1 J8.1 | length 115.9
  L 01 (Top) w0.5: v1(93.925,28.5) D1.1@96.2,28.5 v1(98.475,28.5)
  L 04 (Bot) w2: J8.1@103.75,29.25 103.75,22.625 109.625,16.75 J7.1@111.25,16.75
  L 04 (Bot) w3: J6.3@18,49.83 18.095,49.925 22.225,49.925 34.473,37.677 48.048,37.677 57.05,28.675 93.925,28.675 97.3,28.675 97.8,29.175 97.875,29.25 98.475,29.25 J8.1@103.75,29.25
+VUSB: C2.1 J5.1 J6.1 | length 7.4
  L 01 (Top) w0.3: J5.1@12.75,43.125 14.75,43.125 14.775,43.15 ; 16.05,43.15 16.15,43.05 C2.1@16.15,42.25
  L 01 (Top) w0.5: 14.775,43.15 16.05,43.15 16.4,43.15 J6.1@18,44.75 J6.1@17.65,44.4
/MR: J1.6 S1.1 U1.J5-6 | length 90.8
  L 01 (Top) w0.15: v1(7.95,13.55) v1@7.97,13.53 ; J1.6@7.97,4.52 v1@7.97,13.53 ; S1.1@28.725,35.6 S1.1@20.775,35.6 20.775,29.225 7.97,16.42 7.97,13.55 v1@7.97,13.53 ; U1.J5-6@47.25,21.65 v1(47.25,22.725)
  L 04 (Bot) w0.15: v1(7.95,13.55) 19.8,25.4 40.675,25.4 43.35,22.725 v1(47.25,22.725)
/RESET: J1.8 U1.J5-8 | length 55.2
  L 01 (Top) w0.15: J1.8@10.51,4.52 10.51,14.91 v1(10.525,14.925) ; v1(47.75,20.575) U1.J5-8@47.75,21.65
  L 04 (Bot) w0.15: v1(10.525,14.925) 20.55,24.95 40.25,24.95 43.425,21.775 47.425,21.775 47.75,21.45 v1(47.75,20.575)
B0_IO_A7: J2.38 U1.J4-35 | length 25.7
  L 01 (Top) w0.15: U1.J4-35@55.75,48.35 55.75,52.05 v1(56.225,52.525)
  L 04 (Bot) w0.15: J2.38@48.61,68.02 49.855,66.775 54.35,66.775 56.225,64.9 v1(56.225,52.525)
B0_IO_A8: J2.37 U1.J4-36 | length 16.6
  L 01 (Top) w0.15: J2.37@48.61,65.48 48.635,65.455 48.635,64.465 49.125,63.975 52.3,63.975 55.75,60.525 U1.J4-36@55.75,53.65
B0_IO_A11: J4.7 U1.J4-52 | length 20.6
  L 01 (Top) w0.15: U1.J4-52@59.75,53.65 59.75,60.4 62.425,63.075 69.065,63.075 J4.7@71.47,65.48
B0_IO_A12: J4.15 U1.J4-58 | length 29.5
  L 01 (Top) w0.15: U1.J4-58@61.25,53.65 61.25,60.25 63.025,62.025 70,62.025 71.7,63.725 80.5,63.725 81.63,64.855 J4.15@81.63,65.48
B0_IO_B11: J4.16 U1.J4-56 | length 32.1
  L 01 (Top) w0.15: U1.J4-56@60.75,53.65 60.75,60.6 62.725,62.575 69.8,62.575 71.375,64.15 79.85,64.15 80.375,64.675 80.375,66.765 J4.16@81.63,68.02
B0_IO_C3: J2.5 U1.J4-15 | length 55.4
  L 01 (Top) w0.15: v1(50.75,47.275) U1.J4-15@50.75,48.35
  L 04 (Bot) w0.15: J2.5@7.97,65.48 7.97,62.855 11.85,58.975 37.7,58.975 42.5,54.175 47.275,54.175 48.625,52.825 48.625,48.55 49.9,47.275 v1(50.75,47.275)
B0_IO_C4: J2.6 U1.J4-21 | length 59.3
  L 01 (Top) w0.15: v1(51.775,46.925) 51.775,47.2 52.25,47.675 U1.J4-21@52.25,48.35
  L 04 (Bot) w0.15: J2.6@7.97,68.02 9.175,66.815 9.175,63.4 12.75,59.825 37.9,59.825 42.775,54.95 47.75,54.95 49.075,53.625 49.075,48.875 49.875,48.075 51.2,48.075 51.775,47.5 v1(51.775,46.925)
B0_IO_D13: J4.20 U1.J4-66 | length 33.3
  L 01 (Top) w0.15: U1.J4-66@63.25,53.65 63.25,57.2 65,58.95 80.65,58.95 85.55,63.85 85.55,66.86 J4.20@86.71,68.02
B0_IO_E13: J4.19 U1.J4-68 | length 30.8
  L 01 (Top) w0.15: U1.J4-68@63.75,53.65 63.75,57.1 65.175,58.525 81.275,58.525 86.71,63.96 J4.19@86.71,65.48
B0_IO_G9: J4.8 U1.J4-37 | length 32.8
  L 01 (Top) w0.15: U1.J4-37@56.25,48.35 56.25,49.375 v1(56.55,49.675)
  L 04 (Bot) w0.15: v1(56.55,49.675) 56.875,50 56.875,65.075 58.675,66.875 70.325,66.875 J4.8@71.47,68.02
B0_L01_N: J4.27 U1.J4-75 | length 41
  L 01 (Top) w0.15: U1.J4-75@65.75,48.35 65.75,47.775 65.83,47.695 65.83,47.214 66.334,46.71 78.741,46.71 96.165,64.134 96.165,65.46 96.185,65.48 J4.27@96.87,65.48
B0_L01_P: J4.28 U1.J4-77 | length 42.1
  L 01 (Top) w0.15: U1.J4-77@66.25,48.35 66.25,47.775 66.17,47.695 66.17,47.355 66.475,47.05 78.6,47.05 95.825,64.275 95.825,66.05 96.87,67.095 J4.28@96.87,68.02
B0_L03_N: J4.29 U1.J4-69 | length 46.3
  L 01 (Top) w0.15: U1.J4-69@64.25,48.35 64.25,47.775 64.33,47.695 64.33,46.439 64.835,45.934 64.934,45.835 65.159,45.61 79.666,45.61 98.715,64.659 98.715,65.48 98.715,65.625 99.265,65.625 J4.29@99.41,65.48
B0_L03_P: J4.30 U1.J4-71 | length 47.2
  L 01 (Top) w0.15: U1.J4-71@64.75,48.35 64.75,47.775 64.67,47.695 64.67,46.58 65.075,46.175 65.175,46.075 65.3,45.95 79.525,45.95 98.375,64.8 98.375,66.125 99.41,67.16 J4.30@99.41,68.02
B0_L04_N: J4.31 U1.J4-65 | length 51.1
  L 01 (Top) w0.15: U1.J4-65@63.25,48.35 63.25,47.775 63.33,47.695 63.33,45.514 64.459,44.385 80.791,44.385 101.201,64.795 101.25,64.844 101.25,65.48 101.25,65.5 101.27,65.48 J4.31@101.95,65.48
B0_L04_P: J4.32 U1.J4-67 | length 52.2
  L 01 (Top) w0.15: U1.J4-67@63.75,48.35 63.75,47.775 63.67,47.695 63.67,45.655 64.6,44.725 80.65,44.725 100.9,64.975 100.9,66.05 101.95,67.1 J4.32@101.95,68.02
B0_L05_N: J4.25 U1.J4-61 | length 40.9
  L 01 (Top) w0.15: U1.J4-61@62.25,48.35 62.25,48.925 62.17,49.005 62.17,49.77 62.85,50.45 66.3,50.45 71.725,55.875 85.35,55.875 85.7,56.225 90.175,60.7 90.275,60.8 93.625,64.15 93.625,65.45 93.655,65.48 J4.25@94.33,65.48
B0_L05_P: J4.26 U1.J4-59 | length 43.8
  L 01 (Top) w0.15: U1.J4-59@61.75,48.35 61.75,48.925 61.83,49.005 61.83,49.911 62.709,50.79 66.159,50.79 71.584,56.215 85.209,56.215 ; 85.46,56.465 85.209,56.215 ; 85.559,56.565 85.776,56.782 ; J4.26@94.33,68.02 94.33,67.08 93.285,66.035 93.285,64.291 90.034,61.04 89.935,60.941 85.776,56.782 ; 85.209,56.215 85.776,56.782
B0_L06_N: J4.17 U1.J4-62 | length 31.1
  L 01 (Top) w0.15: U1.J4-62@62.25,53.65 62.25,54.225 62.17,54.305 62.17,59.42 63.425,60.675 63.525,60.775 63.65,60.9 70.856,60.9 72.391,62.435 72.49,62.534 72.666,62.71 82.091,62.71 83.465,64.084 83.465,65.415 83.53,65.48 J4.17@84.17,65.48
B0_L06_P: J4.18 U1.J4-60 | length 33.4
  L 01 (Top) w0.15: U1.J4-60@61.75,53.65 61.75,54.225 61.83,54.305 61.83,59.561 63.185,60.916 63.284,61.015 63.509,61.24 70.715,61.24 72.15,62.675 72.25,62.775 72.525,63.05 81.95,63.05 83.125,64.225 83.125,66.05 84.17,67.095 J4.18@84.17,68.02
B0_L08_N: J4.21 U1.J4-57 | length 39.2
  L 01 (Top) w0.15: U1.J4-57@61.25,48.35 61.25,48.925 61.17,49.005 61.17,50.67 62.025,51.525 66.175,51.525 67.625,52.975 67.725,53.075 67.925,53.275 67.925,55.95 69.325,57.35 82.35,57.35 87.425,62.425 87.525,62.525 88.55,63.55 88.55,65.45 88.58,65.48 J4.21@89.25,65.48
B0_L08_P: J4.22 U1.J4-55 | length 41.5
  L 01 (Top) w0.15: U1.J4-55@60.75,48.35 60.75,48.925 60.83,49.005 60.83,50.811 61.884,51.865 66.034,51.865 67.385,53.216 67.484,53.315 67.585,53.416 67.585,56.091 69.184,57.69 82.209,57.69 87.185,62.666 87.284,62.765 88.21,63.691 88.21,66.06 89.25,67.1 J4.22@89.25,68.02
B0_L09_N: J4.4 U1.J4-48 | length 19.1
  L 01 (Top) w0.15: U1.J4-48@58.75,53.65 58.75,54.225 58.83,54.305 58.83,61.011 61.385,63.566 61.484,63.665 61.859,64.04 64.53,64.04 65.31,64.82 65.31,66.085 66.39,67.165 J4.4@66.39,68.02
B0_L09_P: J4.3 U1.J4-50 | length 16.8
  L 01 (Top) w0.15: U1.J4-50@59.25,53.65 59.25,54.225 59.17,54.305 59.17,60.87 61.625,63.325 61.725,63.425 62,63.7 64.67,63.7 65.65,64.68 65.65,65.425 65.705,65.48 J4.3@66.35,65.48
B0_L15_N: J4.11 U1.J4-51 | length 29.4
  L 01 (Top) w0.15: U1.J4-51@59.75,48.35 59.75,48.925 59.67,49.005 59.67,50.825 v1(59.95,50.825)
  L 04 (Bot) w0.15: v1(59.95,50.825) 59.67,50.825 59.67,51.905 59.325,52.25 59.3,52.275 59.3,54.525 60.525,55.75 60.625,55.85 67.15,62.375 73.95,62.375 75.85,64.275 75.85,65.48 75.85,65.5 76.53,65.5 J4.11@76.55,65.48
B0_L15_P: J4.12 U1.J4-49 | length 31.7
  L 01 (Top) w0.15: v1(59.05,50.825) 59.33,50.825 59.33,49.005 59.25,48.925 U1.J4-49@59.25,48.35
  L 04 (Bot) w0.15: v1(59.05,50.825) 59.33,50.825 59.33,51.764 59.084,52.01 59.06,52.035 58.96,52.134 58.96,54.666 60.285,55.991 60.384,56.09 67.009,62.715 73.809,62.715 75.51,64.416 75.51,65.96 76.55,67 J4.12@76.55,68.02
B0_L17_N: J2.35 U1.J4-30 | length 17.9
  L 01 (Top) w0.15: J2.35@46.07,65.48 46.74,65.48 46.76,65.46 46.76,64.084 46.86,63.985 46.934,63.91 48.034,62.81 51.784,62.81 54.33,60.264 54.33,54.305 54.25,54.225 U1.J4-30@54.25,53.65
B0_L17_P: J2.36 U1.J4-32 | length 20.2
  L 01 (Top) w0.15: J2.36@46.07,68.02 46.07,67.005 47.1,65.975 47.1,64.225 47.175,64.15 48.175,63.15 51.925,63.15 54.67,60.405 54.67,54.305 54.75,54.225 U1.J4-32@54.75,53.65
B0_L18_N: J2.31 U1.J4-26 | length 21.4
  L 01 (Top) w0.15: J2.31@40.99,65.48 41.615,65.48 41.685,65.41 41.685,64.434 42.709,63.41 45.909,63.41 47.509,61.81 51.259,61.81 53.33,59.739 53.33,54.305 53.25,54.225 U1.J4-26@53.25,53.65
B0_L18_P: J2.32 U1.J4-28 | length 23.7
  L 01 (Top) w0.15: J2.32@40.99,68.02 40.99,67.085 42.025,66.05 42.025,64.575 42.85,63.75 46.05,63.75 47.65,62.15 51.4,62.15 53.67,59.88 53.67,54.305 53.75,54.225 U1.J4-28@53.75,53.65
B0_L19_N: J2.28 U1.J4-18 | length 25.4
  L 01 (Top) w0.15: J2.28@35.91,68.02 35.91,67.04 36.95,66 36.95,63.575 41.85,58.675 49.825,58.675 51.17,57.33 51.17,54.305 51.25,54.225 U1.J4-18@51.25,53.65
B0_L19_P: J2.27 U1.J4-16 | length 23.1
  L 01 (Top) w0.15: J2.27@35.91,65.48 36.595,65.48 36.61,65.465 36.61,63.434 41.709,58.335 49.684,58.335 50.83,57.189 50.83,54.305 50.75,54.225 U1.J4-16@50.75,53.65
B0_L20_N: J2.12 U1.J4-31 | length 57.2
  L 01 (Top) w0.15: U1.J4-31@54.75,48.35 54.75,47.775 54.67,47.695 54.67,46.675 v1(54.95,46.675)
  L 04 (Bot) w0.15: J2.12@15.59,68.02 15.59,66.985 16.625,65.95 16.625,64.8 17.425,64 40.125,64 43.325,60.8 43.425,60.7 45.525,58.6 52.55,58.6 53.8,57.35 53.8,51.6 53.825,51.575 53.925,51.475 54.67,50.73 54.67,46.675 v1(54.95,46.675)
B0_L20_P: J2.11 U1.J4-29 | length 54.9
  L 01 (Top) w0.15: v1(54.05,46.675) 54.33,46.675 54.33,47.695 54.25,47.775 U1.J4-29@54.25,48.35
  L 04 (Bot) w0.15: J2.11@15.59,65.48 16.28,65.48 16.285,65.485 16.285,65.48 16.285,64.659 17.284,63.66 39.984,63.66 43.085,60.559 43.184,60.46 45.384,58.26 52.409,58.26 53.46,57.209 53.46,51.459 53.585,51.334 53.684,51.235 54.33,50.589 54.33,46.675 v1(54.05,46.675)
B0_L21_N: J2.29 U1.J4-20 | length 22.5
  L 01 (Top) w0.15: J2.29@38.45,65.48 39.115,65.48 39.16,65.435 39.16,63.934 39.535,63.559 39.634,63.46 40.709,62.385 45.584,62.385 47.334,60.635 50.459,60.635 51.83,59.264 51.83,54.305 51.75,54.225 U1.J4-20@51.75,53.65
B0_L21_P: J2.30 U1.J4-22 | length 24.8
  L 01 (Top) w0.15: J2.30@38.45,68.02 38.45,67 39.5,65.95 39.5,64.075 39.775,63.8 39.875,63.7 40.85,62.725 45.725,62.725 47.475,60.975 50.36,60.975 50.409,61.025 50.55,61.025 52.17,59.405 52.17,54.305 52.25,54.225 U1.J4-22@52.25,53.65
